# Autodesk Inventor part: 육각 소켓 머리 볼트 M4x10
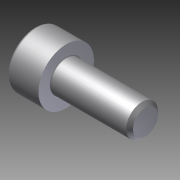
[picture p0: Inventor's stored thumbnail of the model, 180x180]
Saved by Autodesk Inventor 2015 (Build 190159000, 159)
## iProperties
Created: 2024-12
Part Number: 육각 소켓 머리 볼트 M4x10
Material: 일반
Document SubType Name: Modeling
Designer: 102566
Density: 1 g/cm^3
Appearance: 기본값
Author: 102566
Author: jhkim
Description: 6각머리 태핑 나사
Creation Date: 2024-11-28
Sending System: Autodesk Inventor 2025
Preprocessor: ST-DEVELOPER v20
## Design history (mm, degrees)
node "육각 소켓 머리 볼트 M4x101"
body "Solid1"
node "기준1"
